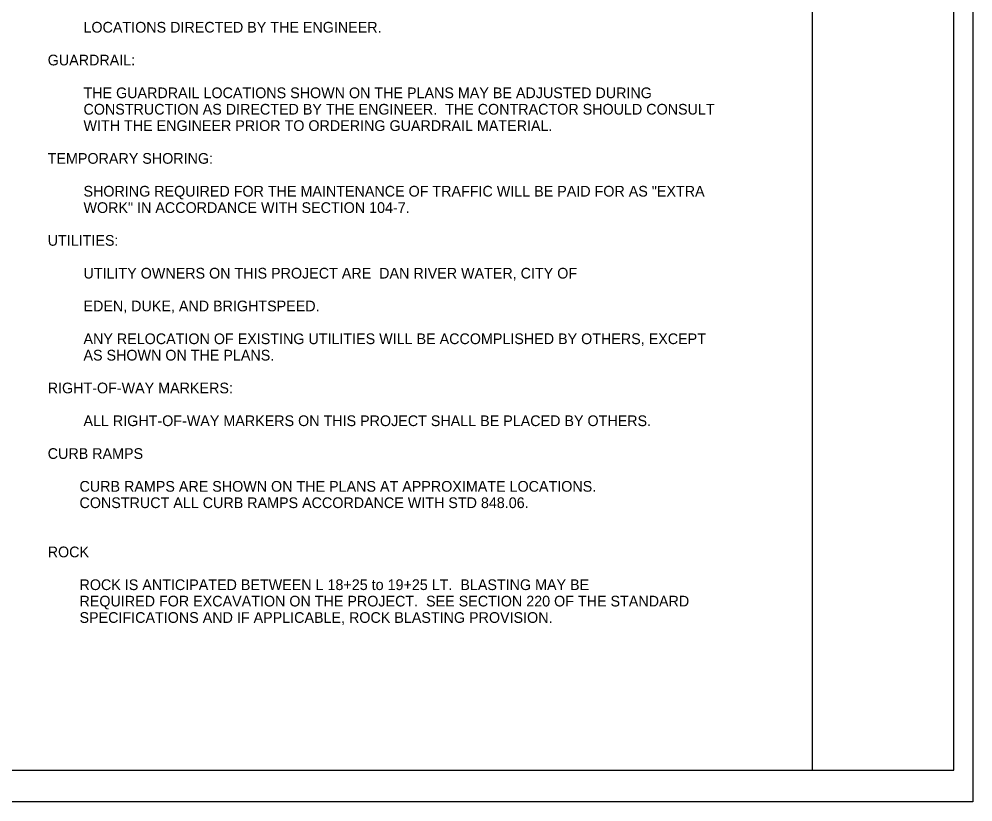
# Model space of a CAD drawing. Extents: x 1184048.9 to 1184122, y 1246638.9 to 1246660.6.
# Drawn here: x 1184101.66 to 1184115.03, y 1246638.86 to 1246649.84 of the extents above; entities that cross this region are included whole.
import ezdxf

# ---------------------------------------------------------------- set-up
doc = ezdxf.new("R2010")
doc.units = 0
for name, color, linetype in [('Sheet Data Field CELL', 7, 'Continuous'), ('Sheet Plan CELL', 7, 'Continuous'), ('Sheet Plot Border Outside CELL', 7, 'Continuous')]:
    doc.layers.add(name, color=color, linetype=linetype)

msp = doc.modelspace()

# ---------------------------------------------------------------- linework, layer by layer
at = {"layer": 'Sheet Plan CELL'}
for p, q in [((1184112.785, 1246639.305), (1184112.786, 1246660.2)), ((1184114.766, 1246639.305), (1184114.767, 1246660.2)), ((1184082.086, 1246639.305), (1184114.766, 1246639.305))]:
    msp.add_line(p, q, dxfattribs=at)
at = {"layer": 'Sheet Plot Border Outside CELL'}
msp.add_lwpolyline([(1184081.364, 1246660.645), (1184115.034, 1246660.645), (1184115.034, 1246638.859), (1184081.364, 1246638.859)], close=True, dxfattribs=at)

# ---------------------------------------------------------------- texts
at = {"layer": 'Sheet Data Field CELL'}
for s, p in [('         LOCATIONS DIRECTED BY THE ENGINEER.  ', (1184102.062, 1246649.651)), ('GUARDRAIL:  ', (1184102.062, 1246649.191)), ('         THE GUARDRAIL LOCATIONS SHOWN ON THE PLANS MAY BE ADJUSTED DURING ', (1184102.062, 1246648.731)), ('         CONSTRUCTION AS DIRECTED BY THE ENGINEER.  THE CONTRACTOR SHOULD CONSULT', (1184102.062, 1246648.501)), ('         WITH THE ENGINEER PRIOR TO ORDERING GUARDRAIL MATERIAL.', (1184102.062, 1246648.271)), ('TEMPORARY SHORING:  ', (1184102.062, 1246647.811)), ('         SHORING REQUIRED FOR THE MAINTENANCE OF TRAFFIC WILL BE PAID FOR AS "EXTRA ', (1184102.062, 1246647.351)), ('         WORK" IN ACCORDANCE WITH SECTION 104-7.  ', (1184102.062, 1246647.121)), ('UTILITIES:  ', (1184102.062, 1246646.661)), ('         UTILITY OWNERS ON THIS PROJECT ARE  DAN RIVER WATER, CITY OF', (1184102.062, 1246646.201)), ('         EDEN, DUKE, AND BRIGHTSPEED.', (1184102.062, 1246645.741)), ('         ANY RELOCATION OF EXISTING UTILITIES WILL BE ACCOMPLISHED BY OTHERS, EXCEPT ', (1184102.062, 1246645.281)), ('         AS SHOWN ON THE PLANS.  ', (1184102.062, 1246645.051)), ('RIGHT-OF-WAY MARKERS:  ', (1184102.062, 1246644.591)), ('         ALL RIGHT-OF-WAY MARKERS ON THIS PROJECT SHALL BE PLACED BY OTHERS.  ', (1184102.062, 1246644.131)), ('CURB RAMPS', (1184102.062, 1246643.671)), ('        CURB RAMPS ARE SHOWN ON THE PLANS AT APPROXIMATE LOCATIONS.', (1184102.062, 1246643.211)), ('        CONSTRUCT ALL CURB RAMPS ACCORDANCE WITH STD 848.06.', (1184102.062, 1246642.981)), ('ROCK', (1184102.062, 1246642.291)), ('        ROCK IS ANTICIPATED BETWEEN L 18+25 to 19+25 LT.  BLASTING MAY BE', (1184102.062, 1246641.831)), ('        REQUIRED FOR EXCAVATION ON THE PROJECT.  SEE SECTION 220 OF THE STANDARD', (1184102.062, 1246641.601)), ('        SPECIFICATIONS AND IF APPLICABLE, ROCK BLASTING PROVISION.', (1184102.062, 1246641.371))]:
    msp.add_text(s, height=0.15, dxfattribs=at).set_placement(p)

doc.saveas('drawing.dxf')
